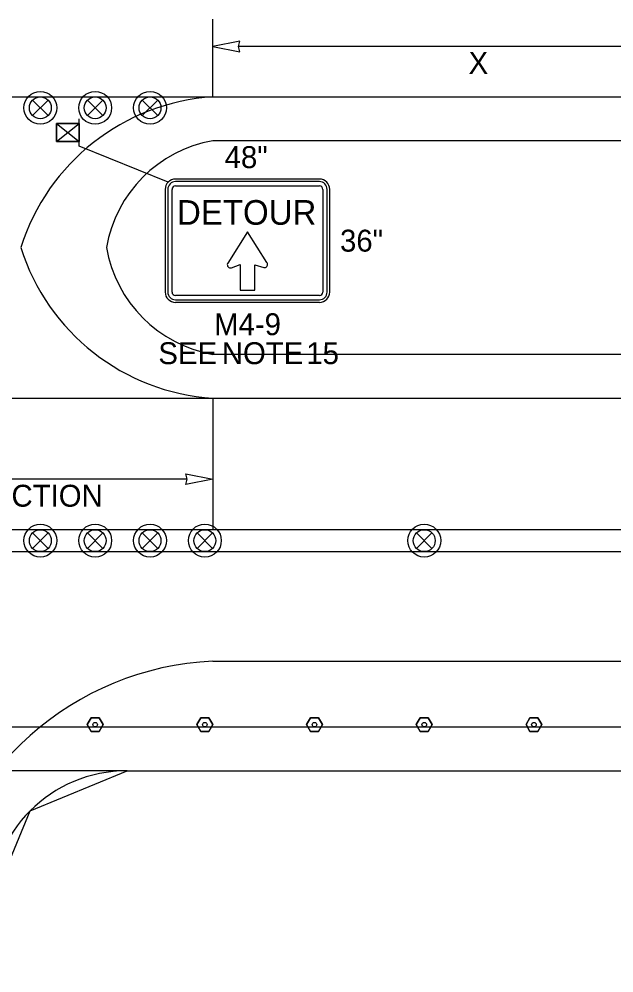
# Model space of a CAD drawing. Extents: x 99958 to 100136, y 99935 to 100013.
# Drawn here: x 100052.192 to 100053.927, y 99973.482 to 99976.268 of the extents above; entities that cross this region are included whole.
import ezdxf

# ---------------------------------------------------------------- set-up
doc = ezdxf.new("R2010")
doc.units = 0
for name, color, linetype in [('RD_ED_ShoulderPavedEdge', 7, 'Continuous'), ('RD_MK_LineEdgeWhite', 7, 'Continuous'), ('RD_MK_LineEdgeYellow', 7, 'Continuous'), ('RD_MK_LineLane', 7, 'Continuous'), ('TR_SN_ConstructionSigns', 7, 'Continuous'), ('TR_WZ_PortableSignMount5ftMinBlk-Org', 7, 'Continuous'), ('TR_WZ_TrafficSafetyDrum', 7, 'Continuous'), ('TR_WZ_TubularMarker', 7, 'Continuous'), ('TR_WZ_WorkZoneDetails', 7, 'Continuous'), ('TR_WZ_WorkZoneTextCurrent', 7, 'Continuous')]:
    doc.layers.add(name, color=color, linetype=linetype)

msp = doc.modelspace()

# ---------------------------------------------------------------- linework, layer by layer
at = {"layer": 'RD_ED_ShoulderPavedEdge'}
for p, q in [((100055.43, 99975.9124), (100052.7569, 99975.9124)), ((100055.43, 99975.2884), (100052.7569, 99975.2884)), ((100052.5069, 99974.0724), (100055.43, 99974.0724))]:
    msp.add_line(p, q, dxfattribs=at)
for centre, radius, start, end in [((100052.8237, 99975.5361), 0.3822, 100.0567, 170.3118), ((100052.8237, 99975.6648), 0.3822, 189.6882, 259.9433), ((100052.5069, 99973.6724), 0.4, 90, 180)]:
    msp.add_arc(centre, radius, start, end, dxfattribs=at)
at = {"layer": 'RD_MK_LineEdgeWhite'}
msp.add_arc((100052.7969, 99973.5319), 0.8615, 92.6555, 170.6116, dxfattribs=at)
at = {"layer": 'RD_MK_LineEdgeYellow'}
for p, q in [((100050.3369, 99976.0404), (100052.7569, 99976.0404)), ((100052.7569, 99976.0404), (100055.43, 99976.0404)), ((100050.3369, 99975.1604), (100052.7569, 99975.1604)), ((100052.7569, 99975.1604), (100055.43, 99975.1604)), ((100052.7569, 99974.3924), (100055.43, 99974.3924))]:
    msp.add_line(p, q, dxfattribs=at)
for centre, start, end in [((100052.7985, 99975.4112), 93.7766, 162.5378), ((100052.7985, 99975.7897), 197.4622, 266.2234)]:
    msp.add_arc(centre, 0.6306, start, end, dxfattribs=at)
at = {"layer": 'RD_MK_LineLane'}
msp.add_lwpolyline([(100055.43, 99974.7764), (100048.195, 99974.7764)], dxfattribs=at)
at = {"layer": 'TR_SN_ConstructionSigns'}
for p, q in [((100053.0681, 99975.8005), (100052.6481, 99975.8005)), ((100052.6181, 99975.7704), (100052.6181, 99975.4704)), ((100052.6256, 99975.7704), (100052.6256, 99975.4704)), ((100052.6381, 99975.4704), (100052.6381, 99975.7704)), ((100053.0681, 99975.793), (100052.6481, 99975.793)), ((100052.6481, 99975.7805), (100053.0681, 99975.7805)), ((100053.0781, 99975.7704), (100053.0781, 99975.4704)), ((100053.0906, 99975.4704), (100053.0906, 99975.7704)), ((100053.0981, 99975.4704), (100053.0981, 99975.7704)), ((100053.0681, 99975.4605), (100052.6481, 99975.4605)), ((100052.6481, 99975.448), (100053.0681, 99975.448)), ((100052.6481, 99975.4405), (100053.0681, 99975.4405))]:
    msp.add_line(p, q, dxfattribs=at)
msp.add_lwpolyline([(100052.8583, 99975.6463), (100052.8007, 99975.5552), (100052.8, 99975.5538), (100052.7994, 99975.5512), (100052.7995, 99975.549), (100052.8001, 99975.5465), (100052.8017, 99975.5439), (100052.8042, 99975.5419), (100052.806, 99975.5412), (100052.8089, 99975.5409), (100052.8114, 99975.5415), (100052.8371, 99975.5505), (100052.8371, 99975.4761), (100052.8795, 99975.4761), (100052.8795, 99975.55), (100052.9059, 99975.5423), (100052.9069, 99975.5421), (100052.9084, 99975.542), (100052.9097, 99975.5422), (100052.9109, 99975.5426), (100052.9123, 99975.5433), (100052.9135, 99975.5441), (100052.9146, 99975.5452), (100052.916, 99975.5475), (100052.9165, 99975.5489), (100052.9167, 99975.55), (100052.9168, 99975.5517), (100052.9165, 99975.5537), (100052.916, 99975.5553), (100052.9151, 99975.5569), (100052.8583, 99975.6463)], dxfattribs=at)
for centre, radius, start, end in [((100052.6481, 99975.7704), 0.03, 90, 180), ((100053.0681, 99975.7704), 0.03, 0, 90), ((100052.6481, 99975.7704), 0.0225, 90, 180), ((100052.6481, 99975.7704), 0.01, 90, 180), ((100053.0681, 99975.7704), 0.0225, 0, 90), ((100053.0681, 99975.7704), 0.01, 0, 90), ((100052.6481, 99975.4704), 0.03, 180, 270), ((100052.6481, 99975.4704), 0.0225, 180, 270), ((100052.6481, 99975.4704), 0.01, 180, 270), ((100053.0681, 99975.4704), 0.03, 270, 0), ((100053.0681, 99975.4704), 0.0225, 270, 0), ((100053.0681, 99975.4704), 0.01, 270, 0)]:
    msp.add_arc(centre, radius, start, end, dxfattribs=at)
at = {"layer": 'TR_WZ_PortableSignMount5ftMinBlk-Org'}
for p, q in [((100052.3673, 99975.8965), (100052.3673, 99975.9765)), ((100052.3006, 99975.9625), (100052.3673, 99975.9105)), ((100052.3006, 99975.9105), (100052.3673, 99975.9625)), ((100052.3338, 99975.9365), (100052.3338, 99975.9365)), ((100052.3339, 99975.9364), (100052.3339, 99975.9364))]:
    msp.add_line(p, q, dxfattribs=at)
for points in [[(100052.3006, 99975.9625), (100052.3006, 99975.9105), (100052.3673, 99975.9105), (100052.3673, 99975.9625)], [(100052.3673, 99975.9105), (100052.3006, 99975.9105), (100052.3006, 99975.9625), (100052.3673, 99975.9625)]]:
    msp.add_lwpolyline(points, close=True, dxfattribs=at)
at = {"layer": 'TR_WZ_TrafficSafetyDrum'}
for p, q in [((100052.2313, 99976.0311), (100052.2765, 99975.9858)), ((100052.2765, 99976.0311), (100052.2313, 99975.9858)), ((100052.3913, 99976.0311), (100052.4365, 99975.9858)), ((100052.4365, 99976.0311), (100052.3913, 99975.9858)), ((100052.5513, 99976.0311), (100052.5965, 99975.9858)), ((100052.5965, 99976.0311), (100052.5513, 99975.9858)), ((100052.2313, 99974.7671), (100052.2765, 99974.7218)), ((100052.2765, 99974.7671), (100052.2313, 99974.7218)), ((100052.3913, 99974.7671), (100052.4365, 99974.7218)), ((100052.4365, 99974.7671), (100052.3913, 99974.7218)), ((100052.5513, 99974.7671), (100052.5965, 99974.7218)), ((100052.5965, 99974.7671), (100052.5513, 99974.7218)), ((100052.7113, 99974.7671), (100052.7565, 99974.7218)), ((100052.7565, 99974.7671), (100052.7113, 99974.7218)), ((100053.3513, 99974.7671), (100053.3965, 99974.7218)), ((100053.3965, 99974.7671), (100053.3513, 99974.7218))]:
    msp.add_line(p, q, dxfattribs=at)
for centre, radius in [((100052.2539, 99976.0085), 0.048), ((100052.2539, 99976.0085), 0.048), ((100052.4139, 99976.0085), 0.048), ((100052.4139, 99976.0085), 0.048), ((100052.5739, 99976.0085), 0.048), ((100052.5739, 99976.0085), 0.048), ((100052.2539, 99976.0085), 0.032), ((100052.4139, 99976.0085), 0.032), ((100052.5739, 99976.0085), 0.032), ((100052.2539, 99974.7445), 0.048), ((100052.2539, 99974.7445), 0.048), ((100052.2539, 99974.7445), 0.032), ((100052.4139, 99974.7445), 0.048), ((100052.4139, 99974.7445), 0.048), ((100052.4139, 99974.7445), 0.032), ((100052.5739, 99974.7445), 0.048), ((100052.5739, 99974.7445), 0.048), ((100052.5739, 99974.7445), 0.032), ((100052.7339, 99974.7445), 0.048), ((100052.7339, 99974.7445), 0.048), ((100052.7339, 99974.7445), 0.032), ((100053.3739, 99974.7445), 0.048), ((100053.3739, 99974.7445), 0.048), ((100053.3739, 99974.7445), 0.032)]:
    msp.add_circle(centre, radius, dxfattribs=at)
at = {"layer": 'TR_WZ_TubularMarker'}
for points in [[(100052.3908, 99974.2071), (100052.4024, 99974.2271), (100052.4255, 99974.2271), (100052.437, 99974.2071), (100052.4255, 99974.1871), (100052.4024, 99974.1871)], [(100052.7108, 99974.2071), (100052.7224, 99974.2271), (100052.7455, 99974.2271), (100052.757, 99974.2071), (100052.7455, 99974.1871), (100052.7224, 99974.1871)], [(100053.0308, 99974.2071), (100053.0424, 99974.2271), (100053.0655, 99974.2271), (100053.077, 99974.2071), (100053.0655, 99974.1871), (100053.0424, 99974.1871)], [(100053.3508, 99974.2071), (100053.3624, 99974.2271), (100053.3855, 99974.2271), (100053.397, 99974.2071), (100053.3855, 99974.1871), (100053.3624, 99974.1871)], [(100053.6708, 99974.2071), (100053.6824, 99974.2271), (100053.7055, 99974.2271), (100053.717, 99974.2071), (100053.7055, 99974.1871), (100053.6824, 99974.1871)]]:
    msp.add_lwpolyline(points, close=True, dxfattribs=at)
for points in [[(100052.4024, 99974.1871), (100052.4255, 99974.1871), (100052.437, 99974.2071), (100052.4255, 99974.2271), (100052.4024, 99974.2271), (100052.3908, 99974.2071), (100052.4024, 99974.1871)], [(100052.7224, 99974.1871), (100052.7455, 99974.1871), (100052.757, 99974.2071), (100052.7455, 99974.2271), (100052.7224, 99974.2271), (100052.7108, 99974.2071), (100052.7224, 99974.1871)], [(100053.0424, 99974.1871), (100053.0655, 99974.1871), (100053.077, 99974.2071), (100053.0655, 99974.2271), (100053.0424, 99974.2271), (100053.0308, 99974.2071), (100053.0424, 99974.1871)], [(100053.3624, 99974.1871), (100053.3855, 99974.1871), (100053.397, 99974.2071), (100053.3855, 99974.2271), (100053.3624, 99974.2271), (100053.3508, 99974.2071), (100053.3624, 99974.1871)], [(100053.6824, 99974.1871), (100053.7055, 99974.1871), (100053.717, 99974.2071), (100053.7055, 99974.2271), (100053.6824, 99974.2271), (100053.6708, 99974.2071), (100053.6824, 99974.1871)]]:
    msp.add_lwpolyline(points, dxfattribs=at)
for centre in [(100052.4139, 99974.2071), (100052.7339, 99974.2071), (100053.0539, 99974.2071), (100053.3739, 99974.2071), (100053.6939, 99974.2071)]:
    msp.add_circle(centre, 0.00667, dxfattribs=at)
at = {"layer": 'TR_WZ_WorkZoneDetails'}
for p, q in [((100052.7569, 99976.0404), (100052.7569, 99976.2677)), ((100054.223, 99976.1876), (100052.8319, 99976.1876)), ((100052.6269, 99975.7917), (100052.3673, 99975.8965)), ((100052.7569, 99975.1604), (100052.7569, 99974.7764)), ((100052.682, 99974.9236), (100050.4119, 99974.9236))]:
    msp.add_line(p, q, dxfattribs=at)
for points in [[(100052.7569, 99976.1876), (100052.8356, 99976.1722), (100052.8319, 99976.1876), (100052.8356, 99976.2031)], [(100052.7569, 99974.9236), (100052.6783, 99974.9082), (100052.682, 99974.9236), (100052.6783, 99974.9391)], [(100048.275, 99974.7114), (100048.275, 99974.2004), (100050.4939, 99974.2004), (100050.8139, 99974.2004), (100050.8139, 99974.2004), (100050.8139, 99974.2004), (100051.1339, 99974.2004), (100051.1339, 99974.2004), (100051.1339, 99974.2004), (100051.7739, 99974.2004), (100052.0939, 99974.2004), (100052.5069, 99974.2004), (100052.5069, 99974.2004), (100055.35, 99974.2004), (100055.35, 99974.7114)], [(100050.5869, 99974.0724), (100050.8698, 99973.9553), (100050.9869, 99973.6724), (100050.9869, 99972.4859), (100050.9869, 99972.4859), (100050.9869, 99972.4859), (100051.5269, 99972.4859), (100051.5269, 99972.4859), (100051.5269, 99972.4859), (100052.1069, 99972.4859), (100052.1069, 99973.6724), (100052.2241, 99973.9553), (100052.2241, 99973.9553), (100052.5069, 99974.0724), (100051.4539, 99974.0724)]]:
    msp.add_lwpolyline(points, close=True, dxfattribs=at)

# ---------------------------------------------------------------- texts
at = {"layer": 'TR_SN_ConstructionSigns'}
for s, height, p in [('48"', 0.064, (100052.7916, 99975.8325)), ('DETOUR', 0.072, (100052.6526, 99975.667)), ('36"', 0.064, (100053.1282, 99975.5885)), ('M4-9', 0.064, (100052.7609, 99975.3445)), ('SEE', 0.064, (100052.5982, 99975.2599)), ('NOTE', 0.064, (100052.7833, 99975.2599)), ('15', 0.064, (100053.0298, 99975.2599))]:
    msp.add_text(s, height=height, rotation=360, dxfattribs=at).set_placement(p)
at = {"layer": 'TR_WZ_WorkZoneTextCurrent'}
for s, p in [('X', (100053.5033, 99976.1077)), ("20' DEVICE SPACING ACROSS INTERSECTION", (100050.5269, 99974.8436))]:
    msp.add_text(s, height=0.064, dxfattribs=at).set_placement(p)

doc.saveas('drawing.dxf')
